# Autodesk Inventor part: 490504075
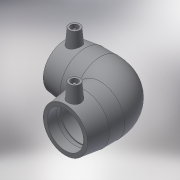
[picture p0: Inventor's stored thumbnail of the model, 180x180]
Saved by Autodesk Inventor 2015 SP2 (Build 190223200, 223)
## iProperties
Created: 2017-06
Part Number: 490504075
Material: Generic
Description: PLASSON 90° ELBOW 75
Document SubType Name: Modeling
Designer: KIM
Mass: 55.0731 g
Surface Area: 148.067 cm^2
Volume: 55.0731 cm^3
Density: 1 g/cm^3
Appearance: Default
Author: KIM
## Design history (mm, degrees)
derived "490504.ipt"
feature "Solid1::490504.ipt"
tag "TaggingFeature1"
body "Solid1"
other parameters: "d2" = 97, "d4" = 39.5, "d5" = 87.3, "d8" = 168 deg, "d10" = 27.6, "d11" = 9.2, "d14" = 17.6296, "d18" = 75, "d19" = 3.52592, "d20" = 168 deg, "d22" = 89.24, "d23" = 97, "d24" = 86.5628, "d29" = 62, "d30" = 15, "d31" = 94.8, "d34" = 5 deg, "d35" = 15, "d39" = 5 deg, "d41" = 4, "d42" = 14, "d43" = 0, "d45" = 4, "d46" = 14, "d47" = 0, "d49" = 75, "d50" = 63.75, "d51" = 27.6, "d52" = 69, "d54" = 90 deg, "d65" = 75, "d67" = 45 deg, "d71" = 90 deg, "d75" = 4.85, "d82" = 45 deg, "d83" = 69, "d84" = 87.3, "d86" = 43.65, "d87" = 90 deg, "d90" = 69, "d91" = 0, "d92" = 69, "d93" = 0, "d94" = 90 deg, "d95" = 44.62, "d98" = 158, "d101" = 3, "d102" = 0, "d103" = 3, "d104" = 0, "d105" = 20.01, "d106" = 5.0025, "d107" = 158, "d110" = 37.95, "d_" = 75, "L_" = 158, "L_1" = 69, "D_" = 97, "A_" = 62, "d_2" = 12
